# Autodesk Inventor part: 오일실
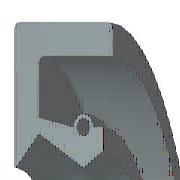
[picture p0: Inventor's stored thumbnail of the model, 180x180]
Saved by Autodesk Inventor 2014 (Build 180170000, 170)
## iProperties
IsCustomPart: 0
Company: 한국ATC센터
Created: 2014-10
Part Number: 오일실
Material: Rubber
Description: 오일-실
Document SubType Name: Modeling
Standard: KS B 2804
Designer: KYOUNG IL JANG
Standards Organization: KS
Language: ko-KR
Size Designation: D - 17 32 8
Categories: <MemberInstance><Categories><Category DisplayName="샤프트 부품" InternalName="7f7aeb1f-a693-4053-b835-cee3144e0d98" Mnemonic="SHFT"><Category DisplayName="실링" Intern
Density: 0.93 g/cm^3
Mass: 2.28027 g
Surface Area: 32.1224 cm^2
Volume: 2.45191 cm^3
Appearance: Rubber - Black - Version 1.1
Author: KYOUNG IL JANG
Revision Number: 1
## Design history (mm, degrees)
revolve "본체" stored, may be unused: angle "d17" = 90 deg
revolve "스프링1" stored, may be unused: angle "d18" = 90 deg
body "Solid1"
sketch "스케치1"
  geometry: L1 (0, 16)-(8, 16); L2 (8, 14.25)-(1.75, 14.25); L3 (1.75, 10.25)-(4.9, 8.5); L4 (4.9, 8.5)-(0, 8.5); L5 (0, 0)-(9.586, 0) reference; L6 (4.9, 8.5)-(6.3, 9.375); L7 (0, 18)-(0, -3) reference; L8 (-1.941, 0)-(11.507, 0) reference; L9 (4.2, 10.6)-(1.75, 11.21); L10 (1.75, 11.21)-(1.75, 14.25); L11 (0, 16)-(0, 8.588); L12 (4.9, 8.5)-(0, 8.5); L13 (1.75, 10.25)-(0.152, 8.528); L14 (8, 16)-(8, 14.25); L15 (5.6, 10.6)-(6.3, 10.6); L16 (6.3, 10.6)-(6.3, 9.375); C1 r 0.455 at (4.9, 10.6); A1 r 0.7 centre (4.9, 10.6) between (5.6, 10.6) and (4.2, 10.6); A2 r 0.088 centre (0.088, 8.588) between (0, 8.588) and (0.152, 8.528); 1 further point
  constraints: 28 end point, 5 horizontal alignment, 5 point on line, 4 point on circle, 4 vertical alignment, 3 centre point, 3 tangent, 2 collinear, 2 horizontal, 2 perpendicular, 1 coincident, 1 parallel
  dimensions: "d0" = 32 diameter of L1 L5 (= SD2); "d1" = 1.75 distance of L1.end L2.start (= SD); "d2" = 0.91 diameter of C1 (= SPDI); "d3" = 1.4 diameter of A1 (= SPDA); "d4" = 17 diameter of L3.end L5 (= NND); "d5" = 20.5 diameter of L3.start L5 (= TKDM); "d7" = 22.42 diameter of L9.end L5 (= TKDM + 0.24 x SWDT); "d8" = 1.75 distance between parallel lines of L11 L10 (= SD); "d9" = 4.9 distance from line of L11 C1.centre (= SPDST); "d10" = 21.2 diameter of C1.centre L5 (= HLDM); "d11" = 0.0875 radius of A2 (= 0.25 x LAB); "d12" = 6.3 distance between parallel lines of L11 L16 (= SDI); "d13" = 18.75 diameter of L6.end L5 (= ABDM); "d14" = 8 distance from line of L11 L1.end (= SWDT)
fillet "모깎기1" dims "d6" = 0.3 (= RR)
other parameters: "SD2" = 32 [user parameter; used in 1 equation term], "SWDT" = 8 [user parameter; used in 2 equation terms], "RR" = 0.3 [user parameter; used in 1 equation term], "SD" = 1.75 [user parameter; used in 2 equation terms], "NND" = 17 [user parameter; used in 1 equation term], "SPDA" = 1.4 [user parameter; used in 1 equation term], "SPDI" = 0.91 [user parameter; used in 1 equation term], "TKDM" = 20.5 [user parameter; used in 2 equation terms], "HLDM" = 21.2 [user parameter; used in 1 equation term], "ABDM" = 18.75 [user parameter; used in 1 equation term], "SDI" = 6.3 [user parameter; used in 1 equation term], "SPDST" = 4.9 [user parameter; used in 1 equation term], "LAB" = 0.35 [user parameter; used in 1 equation term], "d15" = 0, "d16" = 0, "d19" = 0
